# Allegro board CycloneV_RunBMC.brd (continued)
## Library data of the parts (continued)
CB204 = CAP: alternate symbols: (); part number: CAP_0201-0.1UF,6.3V,10%,X6S,C71412-003; tolerance: 10%; room: TEMP_SENSOR
CRB1 = DIODE: part number: DIODE_SM-B0530WS,IC,G70700-001
CT1 = CAP: alternate symbols: (SMX0402C,SMX0402D); part number: CAP_0402-10UF,6.3V,20%,X6S,H80885-001; tolerance: 20%; room: FPGA
CT3 = CAP: alternate symbols: (SMX0402,SMX0402A,SMX0402B); part number: CAP_0402-1.0UF,10V,10%,X6S,D97712-005; tolerance: 10%; room: SMC_EMMC
CT4 CT5 CT8 = CAP: alternate symbols: (); part number: CAP_0201-0.1UF,6.3V,10%,X6S,C71412-003; tolerance: 10%; room: SMC_EMMC
CT6 CT9 = CAP: alternate symbols: (SMX0402,SMX0402A,SMX0402B,SMX0402C); part number: CAP_0402-2.2UF,6.3V,20%,X6S,D97712-006; tolerance: 20%; room: SMC_EMMC
DST1 = LED: part number: LED_A1LF-GREEN,IC,D14725-022; room: FPGA
DST2 = LED_A: part number: LED_A_SMT-ORANGE,IC,E87715-001
EU5C1 = SI5351A: part number: SI5351A_QFN-SI5351A,IC,NNAA
EU8F1 = TPS51200: part number: TPS51200_SM-IC,E17764-001
EU12 U8A6 = USB3320: part number: USB3320_QFN-IC,E67459-001; room: SMC_USB
EUB1 = MX25L51245G: part number: MX25L51245G_SM-IC,J64534-001
EUT1 = PCA9555: part number: PCA9555_QFNLF-IC,D88783-001
EUT2 = MAX34409: part number: MAX34409_LCC-IC,H12741-001
EUT3 = MAX31790: part number: MAX31790_SMT-IC,H59441-001; room: SYS_FAN_CONTROLLER
FB5C1 = FERRITE: alternate symbols: (SMX0603); part number: FERRITE_SMLF-330,FB,693286-052
FB11 FB17 FBB1-FBB4 FBB6 FBB8 FBB12 FBB13 = FERRITE: alternate symbols: (SMX0603); part number: FERRITE_SMLF-30,FB,693286-056
FBB5 FBB7 FBB9-FBB11 = FERRITE: alternate symbols: (SMX0805); part number: FERRITE_SMLF-30,FB,656554-046
J4 = SCONN20_K70426001: part number: SCONN20_K70426001_SM-CONN,K70426-001
J8 = SCONN10_H39949001: part number: SCONN10_H39949001_SM-SCONN,H39949-001
JT1 = SCONN14_D20995012: part number: SCONN14_D20995012_SMT-CONN,D20995-012
JT3 = FCONN260_OCP_BMC: part number: FCONN260_OCP_BMC_FCONN-EMPTY,OCP_BMC
Q3L1 = FET_N_DUAL: part number: FET_N_DUAL_SMLF-NTJD4001N,FET,E40049-001; room: SMC_RESET
Q6A1 Q7A1 = DS1818: part number: DS1818_SOT23LF-IC,C89844-001; room: SMC_RESET
QB1 QT1 = FET_N_DUAL: part number: FET_N_DUAL_SMLF-NTJD4001N,FET,E40049-001
R1A9 R1A11 R2A17 RB75 = RES: alternate symbols: (SMX0402,SMX0402A,SMX0402B); part number: RES_0402-10.0K,1%,1/16W,CHIP,G21796-016; tolerance: 1%; room: SM_MEM
R2A21 R2A22 = RES: alternate symbols: (SMX0402,SMX0402A,SMX0402B); part number: RES_0402-100.0,1%,1/16W,CHIP,G21796-017; tolerance: 1%; room: SM_MEM
R2L48 R2L54 R413 R414 = RES: alternate symbols: (SMX0402,SMX0402A,SMX0402B); part number: RES_0402-0.0,5%,1/16W,CHIP,G21497-005; tolerance: 5%; room: SMC_USB
R3L1 = RES: alternate symbols: (SMX0402,SMX0402A,SMX0402B); part number: RES_0402-4.75K,1%,1/16W,CHIP,G21796-072; tolerance: 1%; room: SMC_RESET
R4L29 R4L39 R7A2 RB19 RB36 = RES: alternate symbols: (SMX0402,SMX0402A,SMX0402B); part number: RES_0402-49.9,1%,1/16W,CHIP,G21796-047; tolerance: 1%; room: SMC_RESET
R4L38 R7A1 = RES: alternate symbols: (SMX0402,SMX0402A,SMX0402B); part number: RES_0402-1.00K,1%,1/16W,CHIP,G21796-026; tolerance: 1%; room: SMC_RESET
R4L40 R4L128 R7A4 RB21 RB169 = RES: alternate symbols: (SMX0402,SMX0402A,SMX0402B); part number: RES_0402-10.0K,1%,1/16W,CHIP,G21796-016; tolerance: 1%; room: SMC_VOL_TRANSLATOR
R5C3 = RES: alternate symbols: (SMX0603); part number: RES_0603-200.0K,1%,1/10W,CHIP,G22026-011; tolerance: 1%; room: SI5338
R5C8 R5C13 R5C14 = RES: alternate symbols: (SMX0402,SMX0402A,SMX0402B); part number: RES_0402-4.75K,1%,1/16W,CHIP,G21796-072; tolerance: 1%; room: SI5338
R5N6 R434 R435 RT102 RT117 RT118 = RES: alternate symbols: (SMX0402,SMX0402A,SMX0402B); part number: RES_0402-0.0,5%,1/16W,CHIP,G21497-005; tolerance: 5%; room: SI5338
R7A52 R395 = RES: alternate symbols: (SMX0402,SMX0402A,SMX0402B); part number: RES_0402-10.0K,1%,1/16W,CHIP,G21796-016; tolerance: 1%; room: SMC_USB
R7A54 R390 R396 R412 = RES: part number: RES_0201-0,1%,1/20W,CHIP,C48657-027; tolerance: 1%; room: SMC_USB
R7A55 R397 = RES: alternate symbols: (SMX0402,SMX0402A,SMX0402B); part number: RES_0402-8.06K,1%,1/16W,CHIP,G21796-078; tolerance: 1%; room: SMC_USB
R7A57 R398 = RES: alternate symbols: (SMX0402,SMX0402A,SMX0402B); part number: RES_0402-1.0M,1%,1/16W,CHIP,G21796-021; tolerance: 1%; room: SMC_USB
R8A43-R8A45 R8A47 R8A49 R8A51 R8A53 R8A55 R399-R406 RB98 RB103 RB140 RB183 RB186 RT2 RT6-RT9 RT44 RT68 RT74 RT95 RT128 RT129 RT132 RT133 = RES: alternate symbols: (SMX0402,SMX0402A,SMX0402B); part number: RES_0402-33.2,1%,1/16W,CHIP,G21796-074; tolerance: 1%; signal model: RES_0402-33.2_1%_1/16W_CHIP_G2A_33.2; room: SMC_USB
R8A56 R8A57 R8A61 R407-R409 = RES: alternate symbols: (SMX0402,SMX0402A,SMX0402B); part number: RES_0402-10.0,1%,1/16W,CHIP,G21796-066; tolerance: 1%; signal model: RES_0402-10.0_1%_1/16W_CHIP_G2A_10.0; room: SMC_USB
R8A64 R410 = RES: part number: RES_0201-0,1%,1/20W,EMPTY,C48657-027; tolerance: 1%; room: SMC_USB
R8F1 = RES: alternate symbols: (SMX0603); part number: RES_0603-10.0,1%,1/10W,CHIP,G22026-041; tolerance: 1%; room: VTT_CPU1_ABC_PWR_VR
R8F3 R8F5 R8F7 R393 R411 RB18 RB24 RB25 RB27 RB29 RB33-RB35 RB38 RB46 RB48 RB49 RB58-RB65 RB68 RB71 RB78 RB91 RB95-RB97 RB102 RB104-RB106 RB109 RB116 RB133 RB135 RB138 RB143 RB148 RB158 RB188-RB190 RT3-RT5 RT11 RT21 RT23-RT25 RT28 RT33-RT36 RT42 RT43 RT46 RT57 RT59 RT70-RT72 RT86-RT91 RT93 RT98-RT100 RT106 RT107 RT114 RT137 = RES: part number: RES_0201-10K,1%,1/20W,CHIP,C48657-004; tolerance: 1%
R8F6 = RES: alternate symbols: (SMX0402,SMX0402A,SMX0402B); part number: RES_0402-0.0,5%,1/16W,CHIP,G21497-005; tolerance: 5%; room: VTT_CPU1_ABC_PWR_VR
R8F8 = RES: alternate symbols: (SMX0402,SMX0402A,SMX0402B); part number: RES_0402-49.9,1%,1/16W,CHIP,G21796-047; tolerance: 1%; room: VTT_CPU1_ABC_PWR_VR
R8F12 = RES: alternate symbols: (SMX0402,SMX0402A,SMX0402B); part number: RES_0402-33.2,1%,1/16W,CHIP,G21796-074; tolerance: 1%; signal model: RES_0402-33.2_1%_1/16W_CHIP_G2A_33.2; room: VTT_CPU0_ABC_PWR_VR
R8L2 = RES: alternate symbols: (SMX0402,SMX0402A,SMX0402B); part number: RES_0402-33.2,1%,1/16W,CHIP,G21796-074; tolerance: 1%; signal model: RES_0402-33.2_1%_1/16W_CHIP_G2A_33.2; room: SMC_RESET
R391 RB126 RB145 RT138-RT140 = RES: alternate symbols: (SMX0402,SMX0402A,SMX0402B); part number: RES_0402-0.0,5%,1/16W,EMPTY,G21497-005; tolerance: 5%
R392 RB86 RB89 RB92 RB108 RB112 RB113 RB119 RB120 RB122 RB125 RB128 RB129 RB134 RB141 RB157 RB172 RB173 RB177 RB184 RB191 RT39 RT50 RT51 RT62 RT66 RT67 = RES: alternate symbols: (SMX0402,SMX0402A,SMX0402B); part number: RES_0402-0.0,5%,1/16W,CHIP,G21497-005; tolerance: 5%
R415 R416 = RES: alternate symbols: (SMX0402,SMX0402A,SMX0402B); part number: RES_0402-120,1%,1/16W,CHIP,G21796-332; tolerance: 1%
R417-R419 = RES: alternate symbols: (SMX0402,SMX0402A,SMX0402B); part number: RES_0402-4.02K,1%,1/16W,CHIP,G21796-082; tolerance: 1%
R420-R422 RB81 RB178 RT69 = RES: alternate symbols: (SMX0402,SMX0402A,SMX0402B); part number: RES_0402-1.00K,1%,1/16W,CHIP,G21796-026; tolerance: 1%
R423 R425 R427 R432 R433 RB23 RB88 RB167 RT47 RT49 RT92 RT97 = RES: alternate symbols: (SMX0402,SMX0402A,SMX0402B); part number: RES_0402-2.0K,1%,1/16W,CHIP,G21796-001; tolerance: 1%
R424 R426 R428 = RES: alternate symbols: (SMX0402,SMX0402A,SMX0402B); part number: RES_0402-499.0,1%,1/16W,CHIP,G21796-139; tolerance: 1%
R429-R431 = RES: alternate symbols: (SMX0402,SMX0402A,SMX0402B); part number: RES_0402-150.0,1%,1/16W,CHIP,G21796-009; tolerance: 1%
R436 = RES: alternate symbols: (SMX0402,SMX0402A,SMX0402B); part number: RES_0402-10.0K,1%,1/16W,EMPTY,G21796-016; tolerance: 1%; room: SM_MEM
RB1-RB17 RB30 RB32 RB37 RB39-RB42 = RES: part number: RES_0201-49.9,1%,1/20W,CHIP,C48657-008; tolerance: 1%
RB20 RB185 RT122 RT123 = RES: alternate symbols: (SMX0402,SMX0402A,SMX0402B); part number: RES_0402-4.75K,1%,1/16W,CHIP,G21796-072; tolerance: 1%
RB22 RB26 RB28 RB51 RB52 RB54 RB55 RB69 RB70 RB100 RB101 RB107 RB110 RB111 RB115 RB118 RB123 RT37 RT48 = RES: alternate symbols: (SMX0402,SMX0402A,SMX0402B); part number: RES_0402-33.2,1%,1/16W,CHIP,G21796-074; tolerance: 1%; signal model: RES_0402-33.2_1%_1/16W_CHIP_G2A_33.2; room: FPGA
RB31 RT105 RT109 RT130 = RES: alternate symbols: (SMX0402,SMX0402A,SMX0402B); part number: RES_0402-1.00K,1%,1/16W,CHIP,G21796-026; tolerance: 1%; room: TEMP_SENSOR
RB43-RB45 RB50 RB56 RB57 RB74 = RES: alternate symbols: (SMX0402,SMX0402A,SMX0402B); part number: RES_0402-240,1.0%,1/16W,CHIP,G21796-294; tolerance: 1.0%
RB47 = RES: alternate symbols: (SMX0402,SMX0402A,SMX0402B); part number: RES_0402-80.6,1.0%,1/16W,CHIP,G21796-282; tolerance: 1.0%
RB53 RT1 RT58 RT60 = RES: part number: RES_0201-1.0K,1%,1/20W,CHIP,C48657-010; tolerance: 1%
RB72 RB73 RB82 RB130 RB131 RB139 RB154 RB179 RB182 RT108 RT112 = RES: part number: RES_0201-49.9K,1.0%,1/20W,CHIP,C48657-079; tolerance: 1%
RB77 RB90 RB181 RT115 = RES: alternate symbols: (SMX0402,SMX0402A,SMX0402B); part number: RES_0402-0.0,5%,1/16W,CHIP,G21497-005; tolerance: 5%; room: SMC_VOL_TRANSLATOR
RB79 RB85 RB127 RB142 RB175 RT20 RT52 RT53 RT61 RT63 RT75 RT78 RT79 RT81 RT83 RT84 RT94 RT96 = RES: alternate symbols: (SMX0402,SMX0402A,SMX0402B); part number: RES_0402-10.0K,1%,1/16W,CHIP,G21796-016; tolerance: 1%
RB80 = RES: alternate symbols: (SMX0402,SMX0402A,SMX0402B); part number: RES_0402-53.6K,1%,1/16W,CHIP,G21796-414; tolerance: 1%
RB84 RT12-RT16 RT18 RT27 RT30 RT38 RT40 RT41 = RES: alternate symbols: (SMX0402,SMX0402A,SMX0402B); part number: RES_0402-10.0,1%,1/16W,CHIP,G21796-066; tolerance: 1%; signal model: RES_0402-10.0_1%_1/16W_CHIP_G2A_10.0; room: SMC_EMMC
RB87 RT73 RT76 RT80 RT82 RT85 = RES: alternate symbols: (SMX0402,SMX0402A,SMX0402B); part number: RES_0402-10.0K,1%,1/16W,EMPTY,G21796-016; tolerance: 1%
RB93 RB117 = RES: alternate symbols: (SMX0402,SMX0402A,SMX0402B); part number: RES_0402-47K,1%,1/16W,CHIP,G21796-354; tolerance: 1%
RB94 RB155 = RES: alternate symbols: (SMX0402,SMX0402A,SMX0402B); part number: RES_0402-100.0K,1%,1/16W,CHIP,G21796-010; tolerance: 1%
RB99 = RES: alternate symbols: (SMX0402,SMX0402A,SMX0402B); part number: RES_0402-2.0K,1%,1/16W,EMPTY,G21796-001; tolerance: 1%
RB114 = RES: alternate symbols: (SMX0402,SMX0402A,SMX0402B); part number: RES_0402-22.1K,1%,1/16W,CHIP,G21796-041; tolerance: 1%
RB121 RB124 RB156 RT65 = RES: alternate symbols: (SMX0402,SMX0402A,SMX0402B); part number: RES_0402-200.0K,1%,1/16W,CHIP,G21796-080; tolerance: 1%
RB132 RB136 RB137 RB146 RB151 RB152 RB160 RB164 RB166 = RES: alternate symbols: (SMX0402,SMX0402A,SMX0402B); part number: RES_0402-4.75K,1%,1/16W,CHIP,G21796-072; tolerance: 1%; room: SYS_FAN_CONTROLLER
RB144 RB147 RB149 RB150 RB153 RB159 RB163 RB165 = RES: alternate symbols: (SMX0402,SMX0402A,SMX0402B); part number: RES_0402-4.75K,1%,1/16W,EMPTY,G21796-072; tolerance: 1%; room: SYS_FAN_CONTROLLER
RB161 RB171 RT101 RT134 = RES: part number: RES_0201-15,1%,1/20W,CHIP,C48657-012; tolerance: 1%
RB162 RT116 = RES: alternate symbols: (SMX0805); part number: RES_0805-0,5%,1/10W,CHIP,108506-002; tolerance: 5%
RB168 = RES: alternate symbols: (SMX0402,SMX0402A,SMX0402B); part number: RES_0402-10.0,1%,1/16W,CHIP,G21796-066; tolerance: 1%; signal model: RES_0402-10.0_1%_1/16W_CHIP_G2A_10.0; room: SMC_VOL_TRANSLATOR
RB180 = RES: alternate symbols: (SMX0402,SMX0402A,SMX0402B); part number: RES_0402-200.0,1%,1/16W,CHIP,G21796-004; tolerance: 1%; room: SMC_VOL_TRANSLATOR
RB187 = RES: part number: RES_0201-49.9,1%,1/20W,CHIP,H36675-043; tolerance: 1%
RT10 = RES: part number: RES_0201-0,1%,1/20W,CHIP,C48657-027; tolerance: 1%
RT31 RT32 = RES: alternate symbols: (SMX0402,SMX0402A,SMX0402B); part number: RES_0402-221,1.0%,1/16W,CHIP,G21796-271; tolerance: 1.0%; room: FPGA
RT45 = RES: alternate symbols: (SMX0402,SMX0402A,SMX0402B); part number: RES_0402-10.0K,1%,1/16W,CHIP,G21796-016; tolerance: 1%; room: VTT_CPU0_ABC_PWR_VR
RT64 = RES: alternate symbols: (SMX0402,SMX0402A,SMX0402B); part number: RES_0402-237.0K,1%,1/16W,CHIP,G21796-115; tolerance: 1%
RT103 RT104 RT131 = RES: alternate symbols: (SMX0402,SMX0402A,SMX0402B); part number: RES_0402-10.0K,1%,1/16W,EMPTY,G21796-016; tolerance: 1%; room: TEMP_SENSOR
RT113 = RES: alternate symbols: (SMX0603); part number: RES_0603-0,5%,1/16W,CHIP,602474-012; tolerance: 5%
RT135 RT136 = RES: part number: RES_0201-10K,1%,1/20W,EMPTY,C48657-004; tolerance: 1%
S7A1 S7A2 = SWITCH_D90553001: part number: SWITCH_D90553001_SMLF-IC,D90553-001; room: SMC_RESET
ST1 = SW_C94015003: part number: SW_C94015003_SOIC-IC,C94015-003
TP1 TP3 TP5 TP7 = TP: part number: TP_TPLF-NA,TP_R30X35T
TP2 TP4 TP6 TP8 = TP: part number: TP_TPLF-NA,TP_R30X35B
U2-U4 = MT41K256M16HA: part number: MT41K256M16HA_BGA-IC,MT41K256M16HA
U7 = TTL1T45: part number: TTL1T45_SMT-IC,G44167-001
U8 = 74CBTLV1G125: part number: 74CBTLV1G125_SMLF-IC,C88177-001
U12 = TTL3257: part number: TTL3257_LCC-74CB3Q3257,IC,H65640-001
UB1 UT1 = TTL2G07: part number: TTL2G07_SC70-74LVC2G07,IC,G93930-001
UB2 UB3 = NC7SB3157: part number: NC7SB3157_SMLF-IC,C99406-001
UB4 = MTFC16GAKAENA: part number: MTFC16GAKAENA_BGA-IC,K29878-001; room: SMC_EMMC
UB5 = 24C02: part number: 24C02_SSOPLF-IC,C47031-001
UT2 UT3 = FET_PCH4D1S: part number: FET_PCH4D1S_SSOP-FDC604P,FET,C22040-001
UT4 = 10M50DA: part number: 10M50DA_BGA-IC,10M50DA
UT5 UT8 = MPM3632: part number: MPM3632_QFN-IC,MPM3632
UT6 = MPM3833: part number: MPM3833_QFN-IC,MPM3833
UT7 = 5CSXFC6: part number: 5CSXFC6_BGA-IC,5CSXFC6
UT9 UT11 = MPM3804: part number: MPM3804_QFN-IC,MPM3804
UT10 = TMP75: part number: TMP75_JICLF-IC,E16415-001; room: TEMP_SENSOR
Y2 Y7A1 = CRYSTAL: part number: CRYSTAL_2013-24.000MHZ,IC,D71700-052; room: SMC_USB
YT1 = CRYSTAL: part number: CRYSTAL_2013LF-25.000MHZ,IC,D71700-033

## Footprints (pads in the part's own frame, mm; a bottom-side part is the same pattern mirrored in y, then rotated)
BGA100_2_1MA
  round 0.432 smd: A1(-4.5,8) A2(-3.5,8) A9(3.5,8) A10(4.5,8) B1(-4.5,7) B10(4.5,7) D2(-3.5,5) D3(-2.5,5) D4(-1.5,5) D5(-0.5,5) D6(0.5,5) D7(1.5,5) D8(2.5,5) D9(3.5,5) E2(-3.5,4) E3(-2.5,4) E4(-1.5,4) E5(-0.5,4) E6(0.5,4) E7(1.5,4) E8(2.5,4) E9(3.5,4) F2(-3.5,3) F3(-2.5,3) F4(-1.5,3) F5(-0.5,3) F6(0.5,3) F7(1.5,3) F8(2.5,3) F9(3.5,3) G2(-3.5,2) G3(-2.5,2) G4(-1.5,2) G5(-0.5,2) G6(0.5,2) G7(1.5,2) G8(2.5,2) G9(3.5,2) H2(-3.5,1) H3(-2.5,1) H4(-1.5,1) H5(-0.5,1) H6(0.5,1) H7(1.5,1) H8(2.5,1) H9(3.5,1) J2(-3.5,0) J3(-2.5,0) J4(-1.5,0) J5(-0.5,0) J6(0.5,0) J7(1.5,0) J8(2.5,0) J9(3.5,0) K2(-3.5,-1) K3(-2.5,-1) K4(-1.5,-1) K5(-0.5,-1) K6(0.5,-1) K7(1.5,-1) K8(2.5,-1) K9(3.5,-1) L2(-3.5,-2) L3(-2.5,-2) L4(-1.5,-2) L5(-0.5,-2) L6(0.5,-2) L7(1.5,-2) L8(2.5,-2) L9(3.5,-2) M2(-3.5,-3) M3(-2.5,-3) M4(-1.5,-3) M5(-0.5,-3) M6(0.5,-3) M7(1.5,-3) M8(2.5,-3) M9(3.5,-3) N2(-3.5,-4) N3(-2.5,-4) N4(-1.5,-4) N5(-0.5,-4) N6(0.5,-4) N7(1.5,-4) N8(2.5,-4) N9(3.5,-4) P2(-3.5,-5) P3(-2.5,-5) P4(-1.5,-5) P5(-0.5,-5) P6(0.5,-5) P7(1.5,-5) P8(2.5,-5) P9(3.5,-5) T1(-4.5,-7) T10(4.5,-7) U1(-4.5,-8) U2(-3.5,-8) U9(3.5,-8) U10(4.5,-8)
BGA256_1_1MB
  round 0.406 smd: A1(0,0) A2(1,0) A3(2,0) A4(3,0) A5(4,0) A6(5,0) A7(6,0) A8(7,0) A9(8,0) A10(9,0) A11(10,0) A12(11,0) A13(12,0) A14(13,0) A15(14,0) A16(15,0) B1(0,-1) B2(1,-1) B3(2,-1) B4(3,-1) B5(4,-1) B6(5,-1) B7(6,-1) B8(7,-1) B9(8,-1) B10(9,-1) B11(10,-1) B12(11,-1) B13(12,-1) B14(13,-1) B15(14,-1) B16(15,-1) C1(0,-2) C2(1,-2) C3(2,-2) C4(3,-2) C5(4,-2) C6(5,-2) C7(6,-2) C8(7,-2) C9(8,-2) C10(9,-2) C11(10,-2) C12(11,-2) C13(12,-2) C14(13,-2) C15(14,-2) C16(15,-2) D1(0,-3) D2(1,-3) D3(2,-3) D4(3,-3) D5(4,-3) D6(5,-3) D7(6,-3) D8(7,-3) D9(8,-3) D10(9,-3) D11(10,-3) D12(11,-3) D13(12,-3) D14(13,-3) D15(14,-3) D16(15,-3) E1(0,-4) E2(1,-4) E3(2,-4) E4(3,-4) E5(4,-4) E6(5,-4) E7(6,-4) E8(7,-4) E9(8,-4) E10(9,-4) E11(10,-4) E12(11,-4) E13(12,-4) E14(13,-4) E15(14,-4) E16(15,-4) F1(0,-5) F2(1,-5) F3(2,-5) F4(3,-5) F5(4,-5) F6(5,-5) F7(6,-5) F8(7,-5) F9(8,-5) F10(9,-5) F11(10,-5) F12(11,-5) F13(12,-5) F14(13,-5) F15(14,-5) F16(15,-5) G1(0,-6) G2(1,-6) G3(2,-6) G4(3,-6) G5(4,-6) G6(5,-6) G7(6,-6) G8(7,-6) G9(8,-6) G10(9,-6) G11(10,-6) G12(11,-6) G13(12,-6) G14(13,-6) G15(14,-6) G16(15,-6) H1(0,-7) H2(1,-7) H3(2,-7) H4(3,-7) H5(4,-7) H6(5,-7) H7(6,-7) H8(7,-7) H9(8,-7) H10(9,-7) H11(10,-7) H12(11,-7) H13(12,-7) H14(13,-7) H15(14,-7) H16(15,-7) J1(0,-8) J2(1,-8) J3(2,-8) J4(3,-8) J5(4,-8) J6(5,-8) J7(6,-8) J8(7,-8) J9(8,-8) J10(9,-8) J11(10,-8) J12(11,-8) J13(12,-8) J14(13,-8) J15(14,-8) J16(15,-8) K1(0,-9) K2(1,-9) K3(2,-9) K4(3,-9) K5(4,-9) K6(5,-9) K7(6,-9) K8(7,-9) K9(8,-9) K10(9,-9) K11(10,-9) K12(11,-9) K13(12,-9) K14(13,-9) K15(14,-9) K16(15,-9) L1(0,-10) L2(1,-10) L3(2,-10) L4(3,-10) L5(4,-10) L6(5,-10) L7(6,-10) L8(7,-10) L9(8,-10) L10(9,-10) L11(10,-10) L12(11,-10) L13(12,-10) L14(13,-10) L15(14,-10) L16(15,-10) M1(0,-11) M2(1,-11) M3(2,-11) M4(3,-11) M5(4,-11) M6(5,-11) M7(6,-11) M8(7,-11) M9(8,-11) M10(9,-11) M11(10,-11) M12(11,-11) M13(12,-11) M14(13,-11) M15(14,-11) M16(15,-11) N1(0,-12) N2(1,-12) N3(2,-12) N4(3,-12) N5(4,-12) N6(5,-12) N7(6,-12) N8(7,-12) N9(8,-12) N10(9,-12) N11(10,-12) N12(11,-12) N13(12,-12) N14(13,-12) N15(14,-12) N16(15,-12) P1(0,-13) P2(1,-13) P3(2,-13) P4(3,-13) P5(4,-13) P6(5,-13) P7(6,-13) P8(7,-13) P9(8,-13) P10(9,-13) P11(10,-13) P12(11,-13) P13(12,-13) P14(13,-13) P15(14,-13) P16(15,-13) R1(0,-14) R2(1,-14) R3(2,-14) R4(3,-14) R5(4,-14) R6(5,-14) R7(6,-14) R8(7,-14) R9(8,-14) R10(9,-14) R11(10,-14) R12(11,-14) R13(12,-14) R14(13,-14) R15(14,-14) R16(15,-14) T1(0,-15) T2(1,-15) T3(2,-15) T4(3,-15) T5(4,-15) T6(5,-15) T7(6,-15) T8(7,-15) T9(8,-15) T10(9,-15) T11(10,-15) T12(11,-15) T13(12,-15) T14(13,-15) T15(14,-15) T16(15,-15)
BGA672_2_8MX
  round 0.406 smd: A2(-10,10.8) A3(-9.2,10.8) A4(-8.4,10.8) A5(-7.6,10.8) A6(-6.8,10.8) A7(-6,10.8) A8(-5.2,10.8) A9(-4.4,10.8) A10(-3.6,10.8) A11(-2.8,10.8) A12(-2,10.8) A13(-1.2,10.8) A14(-0.4,10.8) A15(0.4,10.8) A16(1.2,10.8) A17(2,10.8) A18(2.8,10.8) A19(3.6,10.8) A20(4.4,10.8) A21(5.2,10.8) A22(6,10.8) A23(6.8,10.8) A24(7.6,10.8) A25(8.4,10.8) A26(9.2,10.8) A27(10,10.8) AA1(-10.8,-5.2) AA2(-10,-5.2) AA3(-9.2,-5.2) AA4(-8.4,-5.2) AA5(-7.6,-5.2) AA6(-6.8,-5.2) AA8(-5.2,-5.2) AA9(-4.4,-5.2) AA10(-3.6,-5.2) AA11(-2.8,-5.2) AA12(-2,-5.2) AA13(-1.2,-5.2) AA14(-0.4,-5.2) AA15(0.4,-5.2) AA16(1.2,-5.2) AA17(2,-5.2) AA18(2.8,-5.2) AA19(3.6,-5.2) AA20(4.4,-5.2) AA21(5.2,-5.2) AA23(6.8,-5.2) AA24(7.6,-5.2) AA25(8.4,-5.2) AA26(9.2,-5.2) AA27(10,-5.2) AA28(10.8,-5.2) AB1(-10.8,-6) AB2(-10,-6) AB3(-9.2,-6) AB4(-8.4,-6) AB5(-7.6,-6) AB6(-6.8,-6) AB23(6.8,-6) AB24(7.6,-6) AB25(8.4,-6) AB26(9.2,-6) AB27(10,-6) AB28(10.8,-6) AC1(-10.8,-6.8) AC2(-10,-6.8) AC3(-9.2,-6.8) AC4(-8.4,-6.8) AC5(-7.6,-6.8) AC6(-6.8,-6.8) AC7(-6,-6.8) AC8(-5.2,-6.8) AC21(5.2,-6.8) AC22(6,-6.8) AC23(6.8,-6.8) AC24(7.6,-6.8) AC25(8.4,-6.8) AC26(9.2,-6.8) AC27(10,-6.8) AC28(10.8,-6.8) AD1(-10.8,-7.6) AD2(-10,-7.6) AD3(-9.2,-7.6) AD4(-8.4,-7.6) AD5(-7.6,-7.6) AD6(-6.8,-7.6) AD7(-6,-7.6) AD8(-5.2,-7.6) AD9(-4.4,-7.6) AD10(-3.6,-7.6) AD11(-2.8,-7.6) AD12(-2,-7.6) AD13(-1.2,-7.6) AD14(-0.4,-7.6) AD15(0.4,-7.6) AD16(1.2,-7.6) AD17(2,-7.6) AD18(2.8,-7.6) AD19(3.6,-7.6) AD20(4.4,-7.6) AD21(5.2,-7.6) AD22(6,-7.6) AD23(6.8,-7.6) AD24(7.6,-7.6) AD25(8.4,-7.6) AD26(9.2,-7.6) AD27(10,-7.6) AD28(10.8,-7.6) AE1(-10.8,-8.4) AE2(-10,-8.4) AE3(-9.2,-8.4) AE4(-8.4,-8.4) AE5(-7.6,-8.4) AE6(-6.8,-8.4) AE7(-6,-8.4) AE8(-5.2,-8.4) AE9(-4.4,-8.4) AE10(-3.6,-8.4) AE11(-2.8,-8.4) AE12(-2,-8.4) AE13(-1.2,-8.4) AE14(-0.4,-8.4) AE15(0.4,-8.4) AE16(1.2,-8.4) AE17(2,-8.4) AE18(2.8,-8.4) AE19(3.6,-8.4) AE20(4.4,-8.4) AE21(5.2,-8.4) AE22(6,-8.4) AE23(6.8,-8.4) AE24(7.6,-8.4) AE25(8.4,-8.4) AE26(9.2,-8.4) AE27(10,-8.4) AE28(10.8,-8.4) AF1(-10.8,-9.2) AF2(-10,-9.2) AF3(-9.2,-9.2) AF4(-8.4,-9.2) AF5(-7.6,-9.2) AF6(-6.8,-9.2) AF7(-6,-9.2) AF8(-5.2,-9.2) AF9(-4.4,-9.2) AF10(-3.6,-9.2) AF11(-2.8,-9.2) AF12(-2,-9.2) AF13(-1.2,-9.2) AF14(-0.4,-9.2) AF15(0.4,-9.2) AF16(1.2,-9.2) AF17(2,-9.2) AF18(2.8,-9.2) AF19(3.6,-9.2) AF20(4.4,-9.2) AF21(5.2,-9.2) AF22(6,-9.2) AF23(6.8,-9.2) AF24(7.6,-9.2) AF25(8.4,-9.2) AF26(9.2,-9.2) AF27(10,-9.2) AF28(10.8,-9.2) AG1(-10.8,-10) AG2(-10,-10) AG3(-9.2,-10) AG4(-8.4,-10) AG5(-7.6,-10) AG6(-6.8,-10) AG7(-6,-10) AG8(-5.2,-10) AG9(-4.4,-10) AG10(-3.6,-10) AG11(-2.8,-10) AG12(-2,-10) AG13(-1.2,-10) AG14(-0.4,-10) AG15(0.4,-10) AG16(1.2,-10) AG17(2,-10) AG18(2.8,-10) AG19(3.6,-10) AG20(4.4,-10) AG21(5.2,-10) AG22(6,-10) AG23(6.8,-10) AG24(7.6,-10) AG25(8.4,-10) AG26(9.2,-10) AG27(10,-10) AG28(10.8,-10) AH2(-10,-10.8) AH3(-9.2,-10.8) AH4(-8.4,-10.8) AH5(-7.6,-10.8) AH6(-6.8,-10.8) AH7(-6,-10.8) AH8(-5.2,-10.8) AH9(-4.4,-10.8) AH10(-3.6,-10.8) AH11(-2.8,-10.8) AH12(-2,-10.8) AH13(-1.2,-10.8) AH14(-0.4,-10.8) AH15(0.4,-10.8) AH16(1.2,-10.8) AH17(2,-10.8) AH18(2.8,-10.8) AH19(3.6,-10.8) AH20(4.4,-10.8) AH21(5.2,-10.8) AH22(6,-10.8) AH23(6.8,-10.8) AH24(7.6,-10.8) AH25(8.4,-10.8) AH26(9.2,-10.8) AH27(10,-10.8) B1(-10.8,10) B2(-10,10) B3(-9.2,10) B4(-8.4,10) B5(-7.6,10) B6(-6.8,10) B7(-6,10) B8(-5.2,10) B9(-4.4,10) B10(-3.6,10) B11(-2.8,10) B12(-2,10) B13(-1.2,10) B14(-0.4,10) B15(0.4,10) B16(1.2,10) B17(2,10) B18(2.8,10) B19(3.6,10) B20(4.4,10) B21(5.2,10) B22(6,10) B23(6.8,10) B24(7.6,10) B25(8.4,10) B26(9.2,10) B27(10,10) B28(10.8,10) C1(-10.8,9.2) C2(-10,9.2) C3(-9.2,9.2) C4(-8.4,9.2) C5(-7.6,9.2) C6(-6.8,9.2) C7(-6,9.2) C8(-5.2,9.2) C9(-4.4,9.2) C10(-3.6,9.2) C11(-2.8,9.2) C12(-2,9.2) C13(-1.2,9.2) C14(-0.4,9.2) C15(0.4,9.2) C16(1.2,9.2) C17(2,9.2) C18(2.8,9.2) C19(3.6,9.2) C20(4.4,9.2) C21(5.2,9.2) C22(6,9.2) C23(6.8,9.2) C24(7.6,9.2) C25(8.4,9.2) C26(9.2,9.2) C27(10,9.2) C28(10.8,9.2) D1(-10.8,8.4) D2(-10,8.4) D3(-9.2,8.4) D4(-8.4,8.4) D5(-7.6,8.4) D6(-6.8,8.4) D7(-6,8.4) D8(-5.2,8.4) D9(-4.4,8.4) D10(-3.6,8.4) D11(-2.8,8.4) D12(-2,8.4) D13(-1.2,8.4) D14(-0.4,8.4) D15(0.4,8.4) D16(1.2,8.4) D17(2,8.4) D18(2.8,8.4) D19(3.6,8.4) D20(4.4,8.4) D21(5.2,8.4) D22(6,8.4) D23(6.8,8.4) D24(7.6,8.4) D25(8.4,8.4) D26(9.2,8.4) D27(10,8.4) D28(10.8,8.4) E1(-10.8,7.6) E2(-10,7.6) E3(-9.2,7.6) E4(-8.4,7.6) E5(-7.6,7.6) E6(-6.8,7.6) E7(-6,7.6) E8(-5.2,7.6) E9(-4.4,7.6) E10(-3.6,7.6) E11(-2.8,7.6) E12(-2,7.6) E13(-1.2,7.6) E14(-0.4,7.6) E15(0.4,7.6) E16(1.2,7.6) E17(2,7.6) E18(2.8,7.6) E19(3.6,7.6) E20(4.4,7.6) E21(5.2,7.6) E22(6,7.6) E23(6.8,7.6) E24(7.6,7.6) E25(8.4,7.6) E26(9.2,7.6) E27(10,7.6) E28(10.8,7.6) F1(-10.8,6.8) F2(-10,6.8) F3(-9.2,6.8) F4(-8.4,6.8) F5(-7.6,6.8) F6(-6.8,6.8) F7(-6,6.8) F8(-5.2,6.8) F21(5.2,6.8) F22(6,6.8) F23(6.8,6.8) F24(7.6,6.8) F25(8.4,6.8) F26(9.2,6.8) F27(10,6.8) F28(10.8,6.8) G1(-10.8,6) G2(-10,6) G3(-9.2,6) G4(-8.4,6) G5(-7.6,6) G6(-6.8,6) G23(6.8,6) G24(7.6,6) G25(8.4,6) G26(9.2,6) G27(10,6) G28(10.8,6) H1(-10.8,5.2) H2(-10,5.2) H3(-9.2,5.2) H4(-8.4,5.2) H5(-7.6,5.2) H6(-6.8,5.2) H8(-5.2,5.2) H9(-4.4,5.2) H10(-3.6,5.2) H11(-2.8,5.2) H12(-2,5.2) H13(-1.2,5.2) H14(-0.4,5.2) H15(0.4,5.2) H16(1.2,5.2) H17(2,5.2) H18(2.8,5.2) H19(3.6,5.2) H20(4.4,5.2) H21(5.2,5.2) H23(6.8,5.2) H24(7.6,5.2) H25(8.4,5.2) H26(9.2,5.2) H27(10,5.2) H28(10.8,5.2) J1(-10.8,4.4) J2(-10,4.4) J3(-9.2,4.4) J4(-8.4,4.4) J5(-7.6,4.4) J8(-5.2,4.4) J9(-4.4,4.4) J10(-3.6,4.4) J11(-2.8,4.4) J12(-2,4.4) J13(-1.2,4.4) J14(-0.4,4.4) J15(0.4,4.4) J16(1.2,4.4) J17(2,4.4) J18(2.8,4.4) J19(3.6,4.4) J20(4.4,4.4) J21(5.2,4.4) J24(7.6,4.4) J25(8.4,4.4) J26(9.2,4.4) J27(10,4.4) J28(10.8,4.4) K1(-10.8,3.6) K2(-10,3.6) K3(-9.2,3.6) K4(-8.4,3.6) K5(-7.6,3.6) K8(-5.2,3.6) K9(-4.4,3.6) K10(-3.6,3.6) K11(-2.8,3.6) K12(-2,3.6) K13(-1.2,3.6) K14(-0.4,3.6) K15(0.4,3.6) K16(1.2,3.6) K17(2,3.6) K18(2.8,3.6) K19(3.6,3.6) K20(4.4,3.6) K21(5.2,3.6) K24(7.6,3.6) K25(8.4,3.6) K26(9.2,3.6) K27(10,3.6) K28(10.8,3.6) L1(-10.8,2.8) L2(-10,2.8) L3(-9.2,2.8) L4(-8.4,2.8) L5(-7.6,2.8) L8(-5.2,2.8) L9(-4.4,2.8) L10(-3.6,2.8) L11(-2.8,2.8) L12(-2,2.8) L13(-1.2,2.8) L14(-0.4,2.8) L15(0.4,2.8) L16(1.2,2.8) L17(2,2.8) L18(2.8,2.8) L19(3.6,2.8) L20(4.4,2.8) L21(5.2,2.8) L24(7.6,2.8) L25(8.4,2.8) L26(9.2,2.8) L27(10,2.8) L28(10.8,2.8) M1(-10.8,2) M2(-10,2) M3(-9.2,2) M4(-8.4,2) M5(-7.6,2) M8(-5.2,2) M9(-4.4,2) M10(-3.6,2) M11(-2.8,2) M12(-2,2) M13(-1.2,2) M14(-0.4,2) M15(0.4,2) M16(1.2,2) M17(2,2) M18(2.8,2) M19(3.6,2) M20(4.4,2) M21(5.2,2) M24(7.6,2) M25(8.4,2) M26(9.2,2) M27(10,2) M28(10.8,2) N1(-10.8,1.2) N2(-10,1.2) N3(-9.2,1.2) N4(-8.4,1.2) N5(-7.6,1.2) N8(-5.2,1.2) N9(-4.4,1.2) N10(-3.6,1.2) N11(-2.8,1.2) N12(-2,1.2) N13(-1.2,1.2) N14(-0.4,1.2) N15(0.4,1.2) N16(1.2,1.2) N17(2,1.2) N18(2.8,1.2) N19(3.6,1.2) N20(4.4,1.2) N21(5.2,1.2) N24(7.6,1.2) N25(8.4,1.2) N26(9.2,1.2) N27(10,1.2) N28(10.8,1.2) P1(-10.8,0.4) P2(-10,0.4) P3(-9.2,0.4) P4(-8.4,0.4) P5(-7.6,0.4) P8(-5.2,0.4) P9(-4.4,0.4) P10(-3.6,0.4) P11(-2.8,0.4) P12(-2,0.4) P13(-1.2,0.4) P14(-0.4,0.4) P15(0.4,0.4) P16(1.2,0.4) P17(2,0.4) P18(2.8,0.4) P19(3.6,0.4) P20(4.4,0.4) P21(5.2,0.4) P24(7.6,0.4) P25(8.4,0.4) P26(9.2,0.4) P27(10,0.4) P28(10.8,0.4) R1(-10.8,-0.4) R2(-10,-0.4) R3(-9.2,-0.4) R4(-8.4,-0.4) R5(-7.6,-0.4) R8(-5.2,-0.4) R9(-4.4,-0.4) R10(-3.6,-0.4) R11(-2.8,-0.4) R12(-2,-0.4) R13(-1.2,-0.4) R14(-0.4,-0.4) R15(0.4,-0.4) R16(1.2,-0.4) R17(2,-0.4) R18(2.8,-0.4) R19(3.6,-0.4) R20(4.4,-0.4) R21(5.2,-0.4) R24(7.6,-0.4) R25(8.4,-0.4) R26(9.2,-0.4) R27(10,-0.4) R28(10.8,-0.4) T1(-10.8,-1.2) T2(-10,-1.2) T3(-9.2,-1.2) T4(-8.4,-1.2) T5(-7.6,-1.2) T8(-5.2,-1.2) T9(-4.4,-1.2) T10(-3.6,-1.2) T11(-2.8,-1.2) T12(-2,-1.2) T13(-1.2,-1.2) T14(-0.4,-1.2) T15(0.4,-1.2) T16(1.2,-1.2) T17(2,-1.2) T18(2.8,-1.2) T19(3.6,-1.2) T20(4.4,-1.2) T21(5.2,-1.2) T24(7.6,-1.2) T25(8.4,-1.2) T26(9.2,-1.2) T27(10,-1.2) T28(10.8,-1.2) U1(-10.8,-2) U2(-10,-2) U3(-9.2,-2) U4(-8.4,-2) U5(-7.6,-2) U8(-5.2,-2) U9(-4.4,-2) U10(-3.6,-2) U11(-2.8,-2) U12(-2,-2) U13(-1.2,-2) U14(-0.4,-2) U15(0.4,-2) U16(1.2,-2) U17(2,-2) U18(2.8,-2) U19(3.6,-2) U20(4.4,-2) U21(5.2,-2) U24(7.6,-2) U25(8.4,-2) U26(9.2,-2) U27(10,-2) U28(10.8,-2) V1(-10.8,-2.8) V2(-10,-2.8) V3(-9.2,-2.8) V4(-8.4,-2.8) V5(-7.6,-2.8) V8(-5.2,-2.8) V9(-4.4,-2.8) V10(-3.6,-2.8) V11(-2.8,-2.8) V12(-2,-2.8) V13(-1.2,-2.8) V14(-0.4,-2.8) V15(0.4,-2.8) V16(1.2,-2.8) V17(2,-2.8) V18(2.8,-2.8) V19(3.6,-2.8) V20(4.4,-2.8) V21(5.2,-2.8) V24(7.6,-2.8) V25(8.4,-2.8) V26(9.2,-2.8) V27(10,-2.8) V28(10.8,-2.8) W1(-10.8,-3.6) W2(-10,-3.6) W3(-9.2,-3.6) W4(-8.4,-3.6) W5(-7.6,-3.6) W8(-5.2,-3.6) W9(-4.4,-3.6) W10(-3.6,-3.6) W11(-2.8,-3.6) W12(-2,-3.6) W13(-1.2,-3.6) W14(-0.4,-3.6) W15(0.4,-3.6) W16(1.2,-3.6) W17(2,-3.6) W18(2.8,-3.6) W19(3.6,-3.6) W20(4.4,-3.6) W21(5.2,-3.6) W24(7.6,-3.6) W25(8.4,-3.6) W26(9.2,-3.6) W27(10,-3.6) W28(10.8,-3.6) Y1(-10.8,-4.4) Y2(-10,-4.4) Y3(-9.2,-4.4) Y4(-8.4,-4.4) Y5(-7.6,-4.4) Y8(-5.2,-4.4) Y9(-4.4,-4.4) Y10(-3.6,-4.4) Y11(-2.8,-4.4) Y12(-2,-4.4) Y13(-1.2,-4.4) Y14(-0.4,-4.4) Y15(0.4,-4.4) Y16(1.2,-4.4) Y17(2,-4.4) Y18(2.8,-4.4) Y19(3.6,-4.4) Y20(4.4,-4.4) Y21(5.2,-4.4) Y24(7.6,-4.4) Y25(8.4,-4.4) Y26(9.2,-4.4) Y27(10,-4.4) Y28(10.8,-4.4)
FBGA96_3_8MC
  round 0.356 smd: A1(-3.2,6.001) A2(-2.4,6.001) A3(-1.6,6.001) A7(1.6,6.001) A8(2.4,6.001) A9(3.2,6.001) B1(-3.2,5.201) B2(-2.4,5.201) B3(-1.6,5.201) B7(1.6,5.201) B8(2.4,5.201) B9(3.2,5.201) C1(-3.2,4.401) C2(-2.4,4.401) C3(-1.6,4.401) C7(1.6,4.401) C8(2.4,4.401) C9(3.2,4.401) D1(-3.2,3.6) D2(-2.4,3.6) D3(-1.6,3.6) D7(1.6,3.6) D8(2.4,3.6) D9(3.2,3.6) E1(-3.2,2.8) E2(-2.4,2.8) E3(-1.6,2.8) E7(1.6,2.8) E8(2.4,2.8) E9(3.2,2.8) F1(-3.2,2) F2(-2.4,2) F3(-1.6,2) F7(1.6,2) F8(2.4,2) F9(3.2,2) G1(-3.2,1.2) G2(-2.4,1.2) G3(-1.6,1.2) G7(1.6,1.2) G8(2.4,1.2) G9(3.2,1.2) H1(-3.2,0.4) H2(-2.4,0.4) H3(-1.6,0.4) H7(1.6,0.4) H8(2.4,0.4) H9(3.2,0.4) J1(-3.2,-0.4) J2(-2.4,-0.4) J3(-1.6,-0.4) J7(1.6,-0.4) J8(2.4,-0.4) J9(3.2,-0.4) K1(-3.2,-1.2) K2(-2.4,-1.2) K3(-1.6,-1.2) K7(1.6,-1.2) K8(2.4,-1.2) K9(3.2,-1.2) L1(-3.2,-2) L2(-2.4,-2) L3(-1.6,-2) L7(1.6,-2) L8(2.4,-2) L9(3.2,-2) M1(-3.2,-2.8) M2(-2.4,-2.8) M3(-1.6,-2.8) M7(1.6,-2.8) M8(2.4,-2.8) M9(3.2,-2.8) N1(-3.2,-3.6) N2(-2.4,-3.6) N3(-1.6,-3.6) N7(1.6,-3.6) N8(2.4,-3.6) N9(3.2,-3.6) P1(-3.2,-4.401) P2(-2.4,-4.401) P3(-1.6,-4.401) P7(1.6,-4.401) P8(2.4,-4.401) P9(3.2,-4.401) R1(-3.2,-5.201) R2(-2.4,-5.201) R3(-1.6,-5.201) R7(1.6,-5.201) R8(2.4,-5.201) R9(3.2,-5.201) T1(-3.2,-6.001) T2(-2.4,-6.001) T3(-1.6,-6.001) T7(1.6,-6.001) T8(2.4,-6.001) T9(3.2,-6.001)
FCONN260_OCP_BMC
  rect 0.356x2.261 smd: 1(0,0) 2(0.25,0) 3(0.5,0) 4(0.75,0) 5(1,0) 6(1.25,0) 7(1.5,0) 8(1.75,0) 9(2,0) 10(2.25,0) 11(2.5,0) 12(2.75,0) 13(3,0) 14(3.25,0) 15(3.5,0) 16(3.75,0) 17(4,0) 18(4.25,0) 19(4.5,0) 20(4.75,0) 21(5,0) 22(5.25,0) 23(5.5,0) 24(5.75,0) 25(6,0) 26(6.25,0) 27(6.5,0) 28(6.75,0) 29(7,0) 30(7.25,0) 31(7.5,0) 32(7.75,0) 33(8,0) 34(8.25,0) 35(8.5,0) 36(8.75,0) 37(9,0) 38(9.25,0) 39(9.5,0) 40(9.75,0) 41(10,0) 42(10.25,0) 43(10.5,0) 44(10.75,0) 45(11,0) 46(11.25,0) 47(11.5,0) 48(11.75,0) 49(12,0) 50(12.25,0) 51(12.5,0) 52(12.75,0) 53(13,0) 54(13.25,0) 55(13.5,0) 56(13.75,0) 57(14,0) 58(14.25,0) 59(14.5,0) 60(14.75,0) 61(15,0) 62(15.25,0) 63(15.5,0) 64(15.75,0) 65(16,0) 66(16.25,0) 67(16.5,0) 68(16.75,0) 69(17,0) 70(17.25,0) 71(17.5,0) 72(17.75,0) 73(18,0) 74(18.25,0) 75(18.5,0) 76(18.75,0) 77(19,0) 78(19.25,0) 79(19.5,0) 80(19.75,0) 81(20,0) 82(20.25,0) 83(20.5,0) 84(20.75,0) 85(21,0) 86(21.25,0) 87(21.5,0) 88(21.75,0) 89(22,0) 90(22.25,0) 91(22.5,0) 92(22.75,0) 93(23,0) 94(23.25,0) 95(23.5,0) 96(23.75,0) 97(24,0) 98(24.25,0) 99(24.5,0) 100(24.75,0) 101(25,0) 102(25.25,0) 103(25.5,0) 104(25.75,0) 105(26,0) 106(26.25,0) 107(26.5,0) 108(26.75,0) 109(27,0) 110(27.25,0) 111(27.5,0) 112(27.75,0) 113(28,0) 114(28.25,0) 115(28.5,0) 116(28.75,0) 117(29,0) 118(29.25,0) 119(29.5,0) 120(29.75,0) 121(30,0) 122(30.25,0) 123(30.5,0) 124(30.75,0) 125(31,0) 126(31.25,0) 127(31.5,0) 128(31.75,0) 129(32,0) 130(32.25,0) 131(32.5,0) 132(32.75,0) 133(33,0) 134(33.25,0) 135(33.5,0) 136(33.75,0) 137(34,0) 138(34.25,0) 139(34.5,0) 140(34.75,0) 141(35,0) 142(35.25,0) 143(35.5,0) 144(35.75,0) 145(38,0) 146(38.25,0) 147(38.5,0) 148(38.75,0) 149(39,0) 150(39.25,0) 151(39.5,0) 152(39.75,0) 153(40,0) 154(40.25,0) 155(40.5,0) 156(40.75,0) 157(41,0) 158(41.25,0) 159(41.5,0) 160(41.75,0) 161(42,0) 162(42.25,0) 163(42.5,0) 164(42.75,0) 165(43,0) 166(43.25,0) 167(43.5,0) 168(43.75,0) 169(44,0) 170(44.25,0) 171(44.5,0) 172(44.75,0) 173(45,0) 174(45.25,0) 175(45.5,0) 176(45.75,0) 177(46,0) 178(46.25,0) 179(46.5,0) 180(46.75,0) 181(47,0) 182(47.25,0) 183(47.5,0) 184(47.75,0) 185(48,0) 186(48.25,0) 187(48.5,0) 188(48.75,0) 189(49,0) 190(49.25,0) 191(49.5,0) 192(49.75,0) 193(50,0) 194(50.25,0) 195(50.5,0) 196(50.75,0) 197(51,0) 198(51.25,0) 199(51.5,0) 200(51.75,0) 201(52,0) 202(52.25,0) 203(52.5,0) 204(52.75,0) 205(53,0) 206(53.25,0) 207(53.5,0) 208(53.75,0) 209(54,0) 210(54.25,0) 211(54.5,0) 212(54.75,0) 213(55,0) 214(55.25,0) 215(55.5,0) 216(55.75,0) 217(56,0) 218(56.25,0) 219(56.5,0) 220(56.75,0) 221(57,0) 222(57.25,0) 223(57.5,0) 224(57.75,0) 225(58,0) 226(58.25,0) 227(58.5,0) 228(58.75,0) 229(59,0) 230(59.25,0) 231(59.5,0) 232(59.75,0) 233(60,0) 234(60.25,0) 235(60.5,0) 236(60.75,0) 237(61,0) 238(61.25,0) 239(61.5,0) 240(61.75,0) 241(62,0) 242(62.25,0) 243(62.5,0) 244(62.75,0) 245(63,0) 246(63.25,0) 247(63.5,0) 248(63.75,0) 249(64,0) 250(64.25,0) 251(64.5,0) 252(64.75,0) 253(65,0) 254(65.25,0) 255(65.5,0) 256(65.75,0) 257(66,0) 258(66.25,0) 259(66.5,0) 260(66.75,0)
LCC8_32_24_127MA
  rect 0.813x0.508 smd: 1(0,0) 2(0,-1.27) 3(0,-2.54) 4(0,-3.81) 5(7.798,-3.81) 6(7.798,-2.54) 7(7.798,-1.27) 8(7.798,0)
  rect 4.699x4.597 smd: 9(3.899,-1.905)
LCC10_12_5MB
  rect 0.584x0.279 smd: 1(0,0) 2(0,-0.5) 3(0,-1) 4(0,-1.5) 5(0,-1.999) 6(2.769,-1.999) 7(2.769,-1.5) 8(2.769,-1) 9(2.769,-0.5) 10(2.769,0)
  custom 0.413x0.413 smd: 11(1.384,-1)
LCC16_16_65MA
  rect 0.914x0.356 smd: 1(-1.791,0.975) 2(-1.791,0.325) 3(-1.791,-0.325) 4(-1.791,-0.975) 9(1.791,-0.975) 10(1.791,-0.325) 11(1.791,0.325) 12(1.791,0.975)
  rect 0.356x0.914 smd: 5(-0.975,-1.79) 6(-0.325,-1.79) 7(0.325,-1.79) 8(0.975,-1.79) 13(0.975,1.791) 14(0.325,1.791) 15(-0.325,1.791) 16(-0.975,1.791)
  rect 2.159x2.159 smd: 17(0,0)
LCC20_16_5MC
  custom 0.076x0.076 smd: 1(-1.918,1.001) 2(-1.918,0.5) 3(-1.918,0) 4(-1.918,-0.5) 5(-1.918,-1.001) 6(-1.001,-1.918) 7(-0.5,-1.918) 8(0,-1.918) 9(0.5,-1.918) 10(1.001,-1.918) 11(1.918,-1.001) 12(1.918,-0.5) 13(1.918,0) 14(1.918,0.5) 15(1.918,1.001) 16(1.001,1.918) 17(0.5,1.918) 18(0,1.918) 19(-0.5,1.918) 20(-1.001,1.918)
  rect 2.743x2.743 smd: 21(0,0)
MLFP24_16_5MA
  custom 0.076x0.076 smd: 1(-1.881,1.25) 2(-1.881,0.75) 3(-1.881,0.25) 4(-1.881,-0.25) 5(-1.881,-0.75) 6(-1.881,-1.25) 7(-1.25,-1.881) 8(-0.75,-1.881) 9(-0.25,-1.881) 10(0.25,-1.881) 11(0.75,-1.881) 12(1.25,-1.881) 13(1.881,-1.25) 14(1.881,-0.75) 15(1.881,-0.25) 16(1.881,0.25) 17(1.881,0.75) 18(1.881,1.25) 19(1.25,1.881) 20(0.75,1.881) 21(0.25,1.881) 22(-0.25,1.881) 23(-0.75,1.881) 24(-1.25,1.881)
  rect 2.489x2.489 smd: 25(0,0)
MPM3632
  rect 0.813x0.254 smd: 1(-1.4,1.7) 2(-1.4,1.3) 3(-1.4,0.9) 4(-1.4,0.5) 11(1.4,0.5) 12(1.4,0.9) 13(1.4,1.3) 14(1.4,1.7)
  rect 1.092x0.254 smd: 5(-1.26,0.1) 10(1.26,0.1)
  custom 0.275x0.275 smd: 6(-1.258,-1.25) 8(1.258,-1.25)
  rect 0.254x0.711 smd: 15(1.25,2.451) 20(-1.25,2.451)
  rect 0.254x0.813 smd: 16(0.75,2.4) 17(0.25,2.4) 18(-0.25,2.4) 19(-0.75,2.4)
MPM3804
  rect 0.813x0.254 smd: 1(-0.899,0.75)
  custom 0.175x0.175 smd: 4(-0.95,-0.252) 6(0.95,-0.252)
  rect 0.254x1.092 smd: 5(0,-0.75)
  rect 0.711x0.254 smd: 9(0.95,0.75)
  rect 0.254x0.711 smd: 10(0,0.95)
MPM3833
  rect 0.813x0.203 smd: 1(-1.15,1.35) 2(-1.15,0.9) 3(-1.15,0.45) 4(-1.15,0) 11(1.15,0) 12(1.15,0.45) 13(1.15,0.9) 14(1.15,1.35)
  custom 0.275x0.275 smd: 7(-1.007,-0.901) 8(1.007,-0.901)
  rect 0.254x1.092 smd: 15(0.25,1.5) 16(-0.25,1.5)
QFN16_14_16_5MB
  custom 0.076x0.076 smd: 1(-0.75,1.905) 2(-1.664,1.25) 3(-1.664,0.75) 4(-1.664,0.25) 5(-1.664,-0.25) 6(-1.664,-0.75) 7(-1.664,-1.25) 8(-0.75,-1.905) 9(0.75,-1.905) 10(1.664,-1.25) 11(1.664,-0.75) 12(1.664,-0.25) 13(1.664,0.25) 14(1.664,0.75) 15(1.664,1.25) 16(0.75,1.905)
  rect 2.057x2.54 smd: 17(0,0)
QFN32_20_5ML
  custom 0.076x0.076 smd: 1(-2.394,1.75) 2(-2.394,1.25) 3(-2.394,0.75) 4(-2.394,0.25) 5(-2.394,-0.25) 6(-2.394,-0.75) 7(-2.394,-1.25) 8(-2.394,-1.75) 9(-1.75,-2.394) 10(-1.25,-2.394) 11(-0.75,-2.394) 12(-0.25,-2.394) 13(0.25,-2.394) 14(0.75,-2.394) 15(1.25,-2.394) 16(1.75,-2.394) 17(2.394,-1.75) 18(2.394,-1.25) 19(2.394,-0.75) 20(2.394,-0.25) 21(2.394,0.25) 22(2.394,0.75) 23(2.394,1.25) 24(2.394,1.75) 25(1.75,2.394) 26(1.25,2.394) 27(0.75,2.394) 28(0.25,2.394) 29(-0.25,2.394) 30(-0.75,2.394) 31(-1.25,2.394) 32(-1.75,2.394)
  rect 3.302x3.302 smd: 33(0,0)
SCONN10_H39949001
  rect 2.794x0.737 smd: 1(0,0) 2(4.064,0) 3(0,-1.27) 4(4.064,-1.27) 5(0,-2.54) 6(4.064,-2.54) 7(0,-3.81) 8(4.064,-3.81) 9(0,-5.08) 10(4.064,-5.08)
SCONN14_D20995012
  rect 2.794x0.737 smd: 1(0,0) 2(4.064,0) 3(0,-1.27) 4(4.064,-1.27) 5(0,-2.54) 6(4.064,-2.54) 7(0,-3.81) 8(4.064,-3.81) 9(0,-5.08) 10(4.064,-5.08) 11(0,-6.35) 12(4.064,-6.35) 13(0,-7.62) 14(4.064,-7.62)
SCONN20K_K70426001
  rect 2.794x0.737 smd: 1(0,0) 2(4.064,0) 3(0,-1.27) 4(4.064,-1.27) 5(0,-2.54) 6(4.064,-2.54) 8(4.064,-3.81) 9(0,-5.08) 10(4.064,-5.08) 11(0,-6.35) 12(4.064,-6.35) 13(0,-7.62) 14(4.064,-7.62) 15(0,-8.89) 16(4.064,-8.89) 17(0,-10.16) 18(4.064,-10.16) 19(0,-11.43) 20(4.064,-11.43)
SFB0603A
  rect 0.762x0.889 smd: 1(0,0) 2(0,-1.27)
SFB0805A
  rect 1.27x1.016 smd: 1(0,0) 2(0,-1.778)
SLEDR0603A
  rect 0.762x1.27 smd: 1(0,0) 2(0,-1.778)
SLEDR0603B_CA
  rect 0.94x1.016 smd: A(0,-2.032) C(0,0)
SMC0201A
  rect 0.305x0.33 smd: 1(0,0) 2(0,-0.533)
SMC0402A
  rect 0.508x0.508 smd: 1(0,0) 2(0,-0.889)
SMC0402B
  rect 0.508x0.66 smd: 1(0,0) 2(0.889,0)
SMC0603A
  rect 0.762x0.889 smd: 1(0,0) 2(0,-1.397)
SMC0603C
  rect 0.889x0.991 smd: 1(0,0) 2(1.397,0)
SMC0805C
  rect 1.016x1.346 smd: 1(0,0) 2(1.781,0)
SMR0201A
  rect 0.305x0.33 smd: 1(0,0) 2(0,-0.533)
SMR0402A
  rect 0.508x0.508 smd: 1(0,0) 2(0,-0.889)
SMR0603A
  rect 0.762x0.889 smd: 1(0,0) 2(0,-1.397)
SMR0805A
  rect 1.27x1.016 smd: 1(0,0) 2(0,-1.778)
SMY1310A
  rect 1.041x1.143 smd: 1(0,0) 2(0,-2.1) 3(1.6,-2.1) 4(1.6,0)
SOD323A
  rect 0.406x1.016 smd: 1(0,0) 2(0,-2.286)
SOT23A
  rect 1.27x1.016 smd: 1(0,0) 2(0,-2.032) 3(2.286,-1.016)
SOT363A
  rect 1.016x0.381 smd: 1(0,0) 2(0,-0.65) 3(0,-1.3) 4(1.778,-1.3) 5(1.778,-0.65) 6(1.778,0)
SSOP5_53_65MA
  rect 1.016x0.381 smd: 1(0,0) 2(0,-0.65) 3(0,-1.3) 4(1.778,-1.3) 5(1.778,0)
SSOP6_53_65MA
  rect 1.016x0.381 smd: 1(0,0) 2(0,-0.65) 3(0,-1.3) 4(1.778,-1.3) 5(1.778,-0.65) 6(1.778,0)
SSOP6_53_65MB
  rect 1.27x0.305 smd: 1(0,0) 2(0,-0.65) 3(0,-1.3) 4(2.286,-1.3) 5(2.286,-0.65) 6(2.286,0)
SSOP6_67_95MA
  rect 1.27x0.508 smd: 1(0,0) 2(0,-0.95) 3(0,-1.9) 4(2.54,-1.9) 5(2.54,-0.95) 6(2.54,0)
SSOP8_12_65MB
  rect 1.905x0.305 smd: 1(0,0) 2(0,-0.65) 3(0,-1.3) 4(0,-1.951) 5(3.683,-1.951) 6(3.683,-1.3) 7(3.683,-0.65) 8(3.683,0)
SSOP8_45_65MA
  rect 2.159x0.381 smd: 1(0,0) 2(0,-0.65) 3(0,-1.3) 4(0,-1.951) 5(5.969,-1.951) 6(5.969,-1.3) 7(5.969,-0.65) 8(5.969,0)
SSW2RPB
  rect 1.245x1.727 smd: 1(0,0) 2(0,-4.318)
SSW04RDA
  rect 0.508x1.778 smd: 1(0,0) 2(1.27,0) 3(0,-7.366) 4(1.27,-7.366)
TP_R30X35B
  rect 0.762x0.889 smd: 1(0,0)
TP_R30X35T
  rect 0.762x0.889 smd: 1(0,0)
TQFN28_16_4MB
  rect 0.686x0.203 smd: 1(-1.905,1.2) 2(-1.905,0.8) 3(-1.905,0.4) 4(-1.905,0) 5(-1.905,-0.4) 6(-1.905,-0.8) 7(-1.905,-1.2) 15(1.905,-1.2) 16(1.905,-0.8) 17(1.905,-0.4) 18(1.905,0) 19(1.905,0.4) 20(1.905,0.8) 21(1.905,1.2)
  rect 0.203x0.686 smd: 8(-1.2,-1.905) 9(-0.8,-1.905) 10(-0.4,-1.905) 11(0,-1.905) 12(0.4,-1.905) 13(0.8,-1.905) 14(1.2,-1.905) 22(1.2,1.905) 23(0.8,1.905) 24(0.4,1.905) 25(0,1.905) 26(-0.4,1.905) 27(-0.8,1.905) 28(-1.2,1.905)
  rect 2.692x2.692 smd: 29(0,0)
unnamed
  round 1.8 hole 1.8 unplated: (0,0)

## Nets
AGND_ADC: CB91.2(B) CB96.2(B) CB103.2(B) CB116.2(B) CB120.2(B) CB121.2(B) CB122.2(B) CB124.2(B) CB143.2(B) CB160.2(B) CT11.2(B) CT12.2(B) CT13.2(B) CT15.2(B) CT16.2(B) CT17.2(B) CT18.2(B) CT19.2(B) CT20.2(B) CT21.2(B) CT22.2(B) FBB6.1 UT4.D2 UT4.E2 UT4.F3
GND: C1A6.2(B) C1A7.2(B) C1A8.2(B) C2L16.2(B) C2L17.2(B) C2L18.2(B) C2L24.2(B) C2L25.2(B) C2L26.2(B) C2L31.2(B) C2L34.2(B) C3L11.2(B) C5C1.2(B) C5C2.2(B) C5C5.2(B) C5C6.2(B) C5C7.2(B) C5C8.2(B) C5C13.2(B) C5N17.2(B) C7A14.2(B) C7A15.2(B) C7A16.2(B) C7A17.2(B) C8A30.2(B) C8A31.2(B) C8A32.2(B) C8F1.2(B) C8F2.2(B) C8F3.2(B) C8F4.2(B) C8F5.2(B) C8F6.2(B) C8F7.2(B) C8F8.2(B) C9L13.2(B) C107.2(B) C114.2(B) C305.2(B) C306.2(B) C307.2(B) C308.2(B) C309.2(B) C310.2(B) C311.2(B) C312.2(B) C313.2(B) C314.2(B) C315.2(B) C316.2(B) C317.2(B) C318.2(B) C319.2(B) C320.2(B) C321.2(B) C322.2(B) CB1.2(B) CB2.2(B) CB3.2(B) CB4.2(B) CB5.2(B) CB6.2(B) CB7.2(B) CB8.2(B) CB9.2(B) CB10.2(B) CB11.2(B) CB12.2(B) CB13.2(B) CB14.2(B) CB15.2(B) CB16.2(B) CB17.2(B) CB18.2(B) CB19.2(B) CB20.2(B) CB21.2(B) CB22.2(B) CB23.2(B) CB24.2(B) CB25.2(B) CB26.2(B) CB27.2(B) CB28.2(B) CB29.2(B) CB30.2(B) CB31.2(B) CB32.2(B) CB33.2(B) CB34.2(B) CB35.2(B) CB36.2(B) CB37.2(B) CB38.2(B) CB39.2(B) CB40.2(B) CB41.2(B) CB42.2(B) CB43.2(B) CB44.2(B) CB45.2(B) CB46.2(B) CB47.2(B) CB48.2(B) CB49.2(B) CB50.2(B) CB51.2(B) CB52.2(B) CB53.2(B) CB54.2(B) CB55.2(B) CB56.2(B) CB57.2(B) CB58.2(B) CB59.2(B) CB60.2(B) CB61.2(B) CB62.2(B) CB63.2(B) CB64.2(B) CB65.2(B) CB66.2(B) CB67.2(B) CB68.2(B) CB69.2(B) CB70.2(B) CB71.2(B) CB72.2(B) CB73.2(B) CB74.2(B) CB75.2(B) CB76.2(B) CB77.2(B) CB78.2(B) CB79.2(B) CB80.2(B) CB81.2(B) CB82.2(B) CB83.2(B) CB84.2(B) CB85.2(B) CB86.2(B) CB87.2(B) CB88.2(B) CB89.2(B) CB90.2(B) CB92.2(B) CB93.2(B) CB94.2(B) CB95.2(B) CB97.2(B) CB98.2(B) CB99.2(B) CB100.2(B) CB101.2(B) CB102.2(B) CB104.2(B) CB105.2(B) CB106.2(B) CB107.2(B) CB108.2(B) CB109.2(B) CB110.2(B) CB111.2(B) CB112.2(B) CB113.2(B) CB114.2(B) CB115.2(B) CB117.2(B) CB118.2(B) CB119.2(B) CB123.2(B) CB125.2(B) CB126.2(B) CB127.2(B) CB128.2(B) CB129.2(B) CB130.2(B) CB131.2(B) CB132.2(B) CB133.2(B) CB134.2(B) CB135.2(B) CB136.2(B) CB137.2(B) CB138.2(B) CB139.2(B) CB140.2(B) CB141.2(B) CB142.2(B) CB144.2(B) CB145.2(B) CB146.2(B) CB147.2(B) CB148.2(B) CB149.2(B) CB150.2(B) CB151.2(B) CB152.2(B) CB153.2(B) CB154.2(B) CB155.2(B) CB156.2(B) CB157.2(B) CB158.2(B) CB159.2(B) CB161.2(B) CB162.2(B) CB163.2(B) CB164.2(B) CB165.2(B) CB166.2(B) CB167.2(B) CB168.2(B) CB169.2(B) CB170.2(B) CB171.2(B) CB172.2(B) CB173.2(B) CB174.2(B) CB175.2(B) CB176.2(B) CB177.2(B) CB178.2(B) CB179.2(B) CB180.2(B) CB181.2(B) CB182.2(B) CB183.2(B) CB184.2(B) CB185.2(B) CB186.2(B) CB187.2(B) CB188.2(B) CB189.2(B) CB190.2(B) CB191.2(B) CB192.2(B) CB193.2(B) CB194.2(B) CB195.2(B) CB196.2(B) CB197.2(B) CB198.2(B) CB199.2(B) CB200.2(B) CB201.2(B) CB202.2(B) CB203.2(B) CB204.2(B) CB205.2(B) CB206.2(B) CB207.2(B) CB208.2(B) CB209.2(B) CB211.2(B) CB212.2(B) CB213.2(B) CT1.2(B) CT2.2(B) CT3.2(B) CT4.2(B) CT5.2(B) CT6.2(B) CT7.2(B) CT8.2(B) CT9.2(B) CT10.2(B) CT14.2(B) CT23.2(B) CT24.2(B) CT28.2(B) EU5C1.21 EU8F1.4 EU8F1.8 EU8F1.11 EU12.33 EUB1.4 EUB1.9 EUT1.9 EUT1.25(VSS<1>) EUT2.7 EUT2.17 EUT3.7 EUT3.8 EUT3.29 FBB6.2(B) J4.3 J4.5 J4.11 J4.13 J4.15 J4.17 J4.19 J8.2 J8.10 JT1.8 JT3.8 JT3.9 JT3.11 JT3.24 JT3.33 JT3.39 JT3.45 JT3.51 JT3.52 JT3.57 JT3.58 JT3.64 JT3.110 JT3.114 JT3.126 JT3.127 JT3.132 JT3.133 JT3.139 JT3.145 JT3.151 JT3.157 JT3.163 JT3.185 JT3.191 JT3.197 JT3.203 JT3.212 JT3.215 JT3.221 JT3.226 JT3.227 JT3.232 JT3.233 JT3.238 JT3.239 JT3.245 JT3.251 Q3L1.1 Q3L1.4(SOURCE<0>) Q6A1.3 Q7A1.3 QB1.1 QB1.4(SOURCE<0>) QT1.4(SOURCE<0>) R1A11.2(B) R2A17.1 R5C8.2(B) R5C13.2(B) R5C14.2(B) R7A55.2(B) R8F5.2(B) R397.2(B) R411.1 R429.2(B) R430.2(B) R431.2(B) RB20.2(B) RB43.2(B) RB44.2(B) RB45.2(B) RB48.2(B) RB53.2(B) RB56.2(B) RB58.2(B) RB59.2(B) RB60.2(B) RB61.2(B) RB62.2(B) RB63.2(B) RB64.2(B) RB65.2(B) RB68.2(B) RB74.2(B) RB80.2(B) RB85.2(B) RB89.2(B) RB94.2(B) RB114.2(B) RB121.2(B) RB132.2(B) RB135.2(B) RB136.2(B) RB137.2(B) RB145.2(B) RB146.2(B) RB150.2(B) RB151.2(B) RB152.2(B) RB155.2(B) RB159.2(B) RB163.2(B) RB165.2(B) RB167.1 RB180.2(B) RB187.2(B) RT1.2(B) RT10.2(B) RT20.2(B) RT25.2(B) RT42.2(B) RT60.1 RT64.2(B) RT75.2(B) RT78.2(B) RT80.2(B) RT81.2(B) RT83.2(B) RT85.2(B) RT91.1 RT103.2(B) RT104.2(B) RT123.1 RT130.2(B) S7A1.1 S7A2.1 TP2.1(TP) U2.A9 U2.B1 U2.B3 U2.B9 U2.D1 U2.D8 U2.E1 U2.E2 U2.E8 U2.F9 U2.G1 U2.G8 U2.G9 U2.J2 U2.J8 U2.M1 U2.M9 U2.P1 U2.P9 U2.T1 U2.T9 U3.A9 U3.B1 U3.B3 U3.B9 U3.D1 U3.D8 U3.E1 U3.E2 U3.E8 U3.F9 U3.G1 U3.G8 U3.G9 U3.J2 U3.J8 U3.M1 U3.M9 U3.P1 U3.P9 U3.T1 U3.T9 U4.A9 U4.B1 U4.B3 U4.B9 U4.D1 U4.D8 U4.E1 U4.E2 U4.E8 U4.F9 U4.G1 U4.G8 U4.G9 U4.J2 U4.J8 U4.M1 U4.M9 U4.P1 U4.P9 U4.T1 U4.T9 U7.2 U8.3 U8A6.33 U12.8 U12.17 UB1.2 UB2.2 UB3.2 UB4.G2 UB4.G3 UB4.G4 UB4.G5 UB4.G6 UB4.G7 UB4.G8 UB4.G9 UB4.H2 UB4.H9 UB4.J5 UB4.L3 UB4.L8 UB4.M4 UB4.M7 UB4.P2 UB4.P9(VSSQ<7>) UB5.4 UT1.2 UT4.A1 UT4.A16 UT4.B14 UT4.C8 UT4.C11 UT4.D3 UT4.D6 UT4.E6 UT4.E13 UT4.F15 UT4.G3 UT4.G8 UT4.G10 UT4.H7 UT4.H14 UT4.J10 UT4.K1 UT4.K3 UT4.K7 UT4.K9 UT4.K16 UT4.L14 UT4.M4 UT4.N9 UT4.N12 UT4.N15 UT4.P3 UT4.P7 UT4.R13 UT4.T1 UT4.T10 UT4.T16 UT5.1 UT5.2 UT5.14 UT5.15 UT5.19 UT5.20 UT6.1 UT6.16 UT7.A3 UT7.A10 UT7.AA1 UT7.AA2 UT7.AA3 UT7.AA9 UT7.AA17 UT7.AA25 UT7.AB1 UT7.AB2 UT7.AB3 UT7.AB24 UT7.AB27 UT7.AC1 UT7.AC2 UT7.AC3 UT7.AC26 UT7.AD3 UT7.AD6 UT7.AD8 UT7.AD14 UT7.AD22 UT7.AD25 UT7.AE1 UT7.AE2 UT7.AE3 UT7.AE5 UT7.AE16 UT7.AE18 UT7.AF3 UT7.AF12 UT7.AF16 UT7.AF24 UT7.AG1 UT7.AG2 UT7.AG3 UT7.AG7 UT7.AG17 UT7.AG27 UT7.AH10 UT7.AH20 UT7.B3 UT7.B5 UT7.B7 UT7.B15 UT7.B17 UT7.B20 UT7.B22 UT7.B25 UT7.B27 UT7.C1 UT7.C2 UT7.C3 UT7.C11 UT7.D3 UT7.D9(VREFB8AN08A) UT7.D10 UT7.D13 UT7.D16 UT7.D19 UT7.D21 UT7.E1 UT7.E2 UT7.E3 UT7.E6 UT7.E9 UT7.E19 UT7.E22 UT7.E23 UT7.E24 UT7.E27 UT7.F1 UT7.F2 UT7.F3 UT7.F6 UT7.F23 UT7.G1 UT7.G2 UT7.G3 UT7.H3 UT7.H4 UT7.H5 UT7.H6 UT7.H11 UT7.H15 UT7.H18 UT7.H20 UT7.H24 UT7.H27 UT7.J1 UT7.J2 UT7.J3 UT7.J5 UT7.J9 UT7.K1 UT7.K2 UT7.K3 UT7.K4 UT7.K8 UT7.K11 UT7.K12 UT7.K14 UT7.K16 UT7.K20 UT7.L1 UT7.L2 UT7.L3 UT7.L5 UT7.L8 UT7.L9 UT7.L10 UT7.L13 UT7.L15 UT7.L17 UT7.L19 UT7.L24 UT7.L27 UT7.M3 UT7.M8 UT7.M10 UT7.M11 UT7.M14 UT7.M16 UT7.M20 UT7.N1 UT7.N2 UT7.N3 UT7.N4 UT7.N8 UT7.N13 UT7.N15 UT7.N17 UT7.N19 UT7.P1 UT7.P2 UT7.P3 UT7.P5 UT7.P8 UT7.P9 UT7.P10 UT7.P12 UT7.P16 UT7.P18 UT7.P20 UT7.P25 UT7.R1 UT7.R2 UT7.R3 UT7.R8 UT7.R11 UT7.R13 UT7.R15 UT7.T3 UT7.T10 UT7.T14 UT7.U1 UT7.U2 UT7.U3 UT7.U5 UT7.U12 UT7.U17 UT7.U20 UT7.U24 UT7.U27 UT7.V1 UT7.V2 UT7.V3 UT7.V8 UT7.V9 UT7.V14 UT7.V21 UT7.V26 UT7.W1 UT7.W2 UT7.W3 UT7.W4 UT7.W16 UT7.W18 UT7.Y3 UT7.Y12 UT7.Y14 UT7.Y20 UT7.Y25 UT8.1 UT8.2 UT8.14 UT8.15 UT8.19 UT8.20 UT9.10 UT10.4 UT11.10 Y2.2 Y2.4 Y7A1.2 Y7A1.4 YT1.2 YT1.4
P0V75_AUX: C1A6.1 C1A7.1 C1A8.1 C8F2.1 C9L13.1 CB3.1 EU8F1.3 R8F1.2(B) RB1.2(B) RB2.2(B) RB3.2(B) RB4.2(B) RB5.2(B) RB6.2(B) RB7.2(B) RB8.2(B) RB9.2(B) RB10.2(B) RB11.2(B) RB12.2(B) RB13.2(B) RB14.2(B) RB15.2(B) RB16.2(B) RB17.2(B) RB19.2(B) RB30.2(B) RB32.2(B) RB37.2(B) RB39.2(B) RB40.2(B) RB41.2(B) RB42.2(B)
P0V75_AUX_REFOUT: C8F6.1 CB19.1 CB20.1 CB21.1 CB24.1 CB26.1 CB32.1 CB66.1 CB68.1 EU8F1.6 U2.H1 U2.M8 U3.H1 U3.M8 U4.H1 U4.M8 UT7.H28 UT7.T27
P1V1_AUX: CB93.1 CB111.1 CB113.1 CB114.1 CB128.1 CB130.1 CB142.1 CB145.1 CB146.1 CB148.1 CB150.1 CB151.1 CB152.1 CB153.1 CB155.1 CB157.1 CB159.1 CB161.1 CB162.1 CB165.1 CB167.1 CB168.1 CB171.1 CB172.1 CB174.1 CB175.1 CB176.1 CB178.1 CB180.1 FBB12.1 FBB13.1 RB113.1 RT66.2(B) UT6.8 UT7.J11 UT7.K13 UT7.K15 UT7.K17 UT7.L11 UT7.L12 UT7.L14 UT7.L16 UT7.L18 UT7.M9 UT7.M12 UT7.M13 UT7.M15 UT7.M17 UT7.M18 UT7.M19 UT7.N9 UT7.N10 UT7.N11 UT7.N12 UT7.N14 UT7.N16 UT7.N18 UT7.P11 UT7.P13 UT7.P14 UT7.P15 UT7.P17 UT7.P19 UT7.R9 UT7.R10 UT7.R12 UT7.R14 UT7.T9 UT7.T15 UT7.U21 UT7.U26
P1V1_AUX_VCCEGXB: CB187.1 CB191.1 CB192.1 CB193.1 CB194.1 CB198.1 FBB13.2(B) UT7.M5 UT7.N5 UT7.R5 UT7.T5
P1V1_AUX_VCCLGXB: CB200.1 CB202.1 CB208.1 CB211.1 FBB12.2(B) UT7.L4 UT7.T4
P1V2_AUX: CB71.1 CB79.1 CB80.1 CB81.1 CB82.1 CB98.1 CB99.1 CB100.1 CB108.1 CB109.1 CB117.1 CT23.1 FBB1.1 RB129.1 U7.1 U7.5 UT4.F6 UT4.G7 UT4.G9 UT4.H8 UT4.H9 UT4.H10 UT4.J7 UT4.J8 UT4.J9 UT4.K8 UT4.K10 UT9.6
P1V2_AUX_PLL: CB62.1 CB63.1 CB129.1 CB137.1 FBB1.2(B) UT4.D4 UT4.D13 UT4.M5 UT4.N13
P1V5_AUX: C8F1.1 C8F3.1 CB4.1 CB5.1 CB6.1 CB7.1 CB8.1 CB9.1 CB10.1 CB11.1 CB12.1 CB13.1 CB15.1 CB16.1 CB25.1 CB27.1 CB28.1 CB29.1 CB30.1 CB31.1 CB34.1 CB35.1 CB37.1 CB38.1 CB39.1 CB40.1 CB42.1 CB43.1 CB44.1 CB45.1 CB46.1 CB47.1 CB48.1 CB49.1 CB50.1 CB52.1 CB53.1 CB54.1 CB67.1 CB73.1 CB74.1 CB77.1 CB84.1 CB94.1 CB95.1 CB102.1 CB125.1 CB126.1 EU8F1.2 R8F3.1 RB23.2(B) RB50.1 RB57.1 RB81.2(B) RB92.1 U2.A1 U2.A8 U2.B2 U2.C1 U2.C9 U2.D2 U2.D9 U2.E9 U2.F1 U2.G7 U2.H2 U2.H9 U2.K2 U2.K8 U2.N1 U2.N9 U2.R1 U2.R9 U3.A1 U3.A8 U3.B2 U3.C1 U3.C9 U3.D2 U3.D9 U3.E9 U3.F1 U3.G7 U3.H2 U3.H9 U3.K2 U3.K8 U3.N1 U3.N9 U3.R1 U3.R9 U4.A1 U4.A8 U4.B2 U4.C1 U4.C9 U4.D2 U4.D9 U4.E9 U4.F1 U4.G7 U4.H2 U4.H9 U4.K2 U4.K8 U4.N1 U4.N9 U4.R1 U4.R9 UT5.8 UT7.AD27 UT7.C25 UT7.C27 UT7.F27 UT7.G24 UT7.H21 UT7.H26 UT7.L26 UT7.M21 UT7.P27 UT7.T21 UT7.T25 UT7.U18 UT7.W27
P1V8_AUX: C2L34.1 C308.1 CT24.1 R2L54.1 R413.1 RB157.1 UT11.6
P1V8_P3V3_GPPA_AUX: CB179.1 CB188.1 UT2.1 UT2.2 UT2.5 UT2.6 UT7.AA5 UT7.W9
P1V8_P3V3_GPPA_AUX_EDGE: JT3.152(VDD_LPC3V3_ESPI1V8) UT2.4(S)
P1V8_USBPHY_AUX: C2L24.1 C2L25.1 C2L26.1 C2L31.1 R2L54.2(B) U8A6.28 U8A6.30
P1V8_USBPHY_USB2B_AUX: C312.1 C313.1 C314.1 C315.1 EU12.28 EU12.30 R413.2(B)
P2V5_3V3_VCCPD3A: RB108.1 RB126.1 UT7.AA10
P2V5_AUX: CB65.1 CB69.1 CB87.1 CB101.1 CB104.1 CB118.1 CB133.1 CB163.1 CB164.1 FBB3.1 FBB8.1 RB108.2(B) RB120.1 RT69.2(B) UT4.D5 UT4.E12 UT4.L5 UT4.M12 UT7.K21 UT7.K24 UT7.M24 UT7.P21 UT7.P24 UT8.8
P2V5_AUX_ADCVREF: CB116.1 CB124.1 FBB4.2(B) UT4.E4
P2V5_AUX_FILT: CB92.1 CB105.1 CB107.1 CB135.1 CB149.1 CB177.1 CB181.1 CB183.1 CB189.1 CB195.1 CB203.1 CB205.1 FBB3.2(B) UT7.AA21 UT7.AC8 UT7.AC21 UT7.AD15 UT7.D7 UT7.E15 UT7.F8 UT7.F21 UT7.H23 UT7.J4 UT7.K5 UT7.M4 UT7.P4 UT7.R4 UT7.U4 UT7.W5
P2V5_AUX_VCCADC: CB121.1 CB122.1 CB160.1 FBB4.1 FBB8.2(B) UT4.E5
P3V3_AUX: C8A30.1 C8A31.1 C8A32.1 C309.1 C310.1 C311.1 CB36.1 CB41.1 CB185.1 CB186.1 CB197.1 CB204.1 CRB1.2 CT1.1 CT2.1 CT4.1 CT6.1 CT8.1 CT9.1 CT28.1 DST1.1 DST2.A EU12.21 EUT1.21 EUT2.15(VDD) EUT3.21 FB5C1.1 FBB5.1 FBB9.1 FBB10.1 J4.1 J8.4 R1A9.2(B) R2L48.1 R3L1.1 R4L38.1 R4L40.1 R4L128.1 R7A1.1 R7A4.1 R7A54.1 R8F6.1 R8F7.1 R393.1 R396.1 R414.1 R432.1 R433.1 R436.2(B) RB21.1 RB24.1 RB25.2(B) RB27.1 RB31.1 RB33.1 RB34.2(B) RB46.1 RB49.1 RB72.1 RB73.1 RB78.1 RB82.1 RB87.1 RB88.2(B) RB91.2(B) RB95.2(B) RB96.2(B) RB97.2(B) RB102.2(B) RB104.2(B) RB105.2(B) RB106.2(B) RB109.2(B) RB116.2(B) RB127.1 RB130.1 RB131.1 RB133.2(B) RB138.2(B) RB139.1 RB142.1 RB143.2(B) RB144.1 RB147.1 RB148.2(B) RB149.1 RB153.1 RB154.1 RB158.1 RB160.1 RB162.2(B) RB164.1 RB166.1 RB169.1 RB175.1 RB178.1 RB179.1 RB182.1 RB185.1 RB188.2(B) RB189.2(B) RB190.2(B) RT3.1 RT4.1 RT5.1 RT11.2(B) RT21.2(B) RT23.2(B) RT24.1 RT33.2(B) RT35.2(B) RT36.2(B) RT43.2(B) RT45.1 RT46.2(B) RT47.2(B) RT49.2(B) RT52.1 RT53.1 RT57.2(B) RT58.1 RT59.2(B) RT61.1 RT63.1 RT70.2(B) RT71.1 RT72.2(B) RT86.2(B) RT88.2(B) RT89.2(B) RT90.2(B) RT92.2(B) RT93.2(B) RT94.1 RT96.1 RT97.2(B) RT98.2(B) RT99.2(B) RT100.1 RT101.1 RT105.1 RT106.1 RT107.1 RT108.1 RT109.1 RT112.1 RT114.2(B) RT122.1 RT131.1 RT135.2(B) RT136.2(B) RT137.2(B) U7.6(VCCB) U8.5 U8A6.21 U12.16(VCC) UB1.5 UB2.5(VCC) UB3.5(VCC) UB4.F2 UB4.F3 UB4.F4 UB4.F5 UB4.F6 UB4.F7 UB4.F8 UB4.F9 UB4.H3 UB4.H8 UB4.L2 UB4.L4 UB4.L7 UB4.L9 UB4.P3 UB4.P8 UB5.8 UT1.5 UT3.4(S) UT10.8(VCC)
P3V3_AUX_EDGE: JT3.3 JT3.4 JT3.5 JT3.6 JT3.7 RB161.1 RB162.1
P3V3_AUX_IO: CB56.1 CB57.1 CB58.1 CB59.1 CB60.1 CB61.1 CB64.1 CB70.1 CB72.1 CB75.1 CB76.1 CB78.1 CB83.1 CB85.1 CB89.1 CB90.1 CB106.1 CB110.1 CB119.1 CB123.1 CB132.1 CB134.1 CB136.1 CB138.1 CB139.1 CB140.1 CB141.1 CB154.1 CB156.1 CB158.1 CB170.1 CB190.1 CB196.1 FBB2.1 RB71.2(B) RB75.2(B) RB79.1 RB99.1 RB126.2(B) RT28.2(B) RT34.2(B) RT73.1 RT76.1 RT79.1 RT82.1 RT84.1 RT87.1 UT3.1 UT3.2 UT3.5 UT3.6 UT4.C7(VCCIO8<2>) UT4.D7 UT4.D8 UT4.D10 UT4.D11 UT4.F13 UT4.G13 UT4.H13 UT4.J4 UT4.J13 UT4.K4 UT4.K13 UT4.L4 UT4.L13 UT4.M13 UT4.N6 UT4.N7 UT4.N8 UT4.N10 UT4.N11 UT7.AA12 UT7.AA14 UT7.AA16 UT7.AC25 UT7.AD9 UT7.AD13 UT7.AD16 UT7.AD18 UT7.AD21 UT7.AD24 UT7.AE10 UT7.AE13 UT7.AE21 UT7.AF14 UT7.AF19 UT7.AG4 UT7.AG12 UT7.AG22 UT7.AH15 UT7.AH25 UT7.B10 UT7.B13 UT7.C20 UT7.D6 UT7.D18 UT7.E7 UT7.E10 UT7.E13 UT7.E14 UT7.E17 UT7.E21 UT7.F22 UT7.G5 UT7.H10 UT7.H14 UT7.J19 UT7.W13 UT7.W17 UT7.W19 UT7.W25 UT7.Y10 UT7.Y21
